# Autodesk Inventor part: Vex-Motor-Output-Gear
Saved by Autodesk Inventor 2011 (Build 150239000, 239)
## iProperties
Created: 2007-08
Part Number: Vex-Motor-Output-Gear
Document SubType Name: Modeling
Density: 1 g/cm^3
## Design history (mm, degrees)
feature "Base1"
body "Solid1"
